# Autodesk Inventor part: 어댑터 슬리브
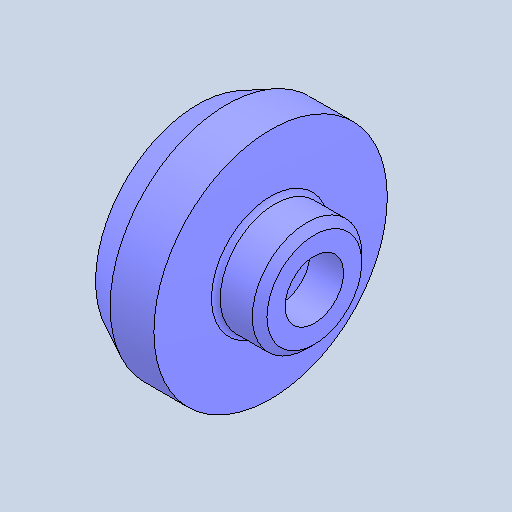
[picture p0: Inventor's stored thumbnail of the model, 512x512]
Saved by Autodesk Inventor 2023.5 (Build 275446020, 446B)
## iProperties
Created: 2026-07
Part Number: 어댑터 슬리브
Material: 강철, 탄소
Document SubType Name: Modeling
Designer: 1강의실14
Density: 7.87 g/cm^3
Appearance: 기본값
Author: jhkim
Sending System: Autodesk Inventor 2027
Preprocessor: ST-DEVELOPER v20.1
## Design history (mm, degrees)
node "어댑터 슬리브1"
node "솔리드2"
node "솔리드1"
